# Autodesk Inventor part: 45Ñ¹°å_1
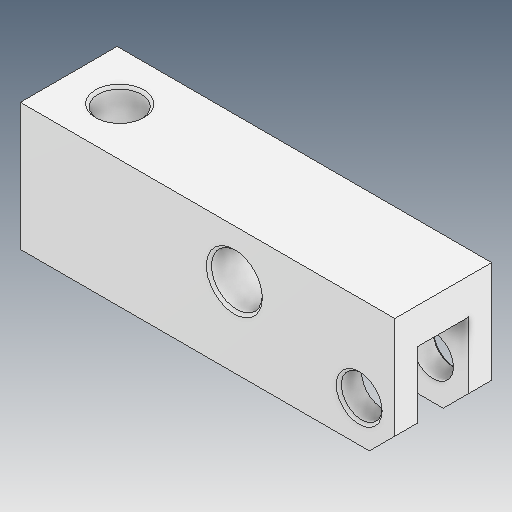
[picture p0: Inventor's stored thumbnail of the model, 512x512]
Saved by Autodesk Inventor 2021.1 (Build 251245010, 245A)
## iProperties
Created: 2021-05
Part Number: 45Ñ¹°å_1
Material: Ogólny
Document SubType Name: Modeling
Designer: user
Density: 1 g/cm^3
Appearance: Domyślna
Author: user
Revision Number: ÈÎºÎ
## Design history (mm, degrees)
feature "ÊäÈë1"
node "Bryła1"
